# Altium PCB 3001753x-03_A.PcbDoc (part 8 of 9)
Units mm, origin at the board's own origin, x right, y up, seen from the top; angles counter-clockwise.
Board outline 210 x 130 mm, 8 copper layers (1-TOP, 2-GND, 3-INTOP, 4-PWR, 5-PWR, 6-INBOT, 7-GND, 8-BOTTOM), stack 1.646 mm thick; 676 components, 623 nets, 2861 pads, 2382 vias.
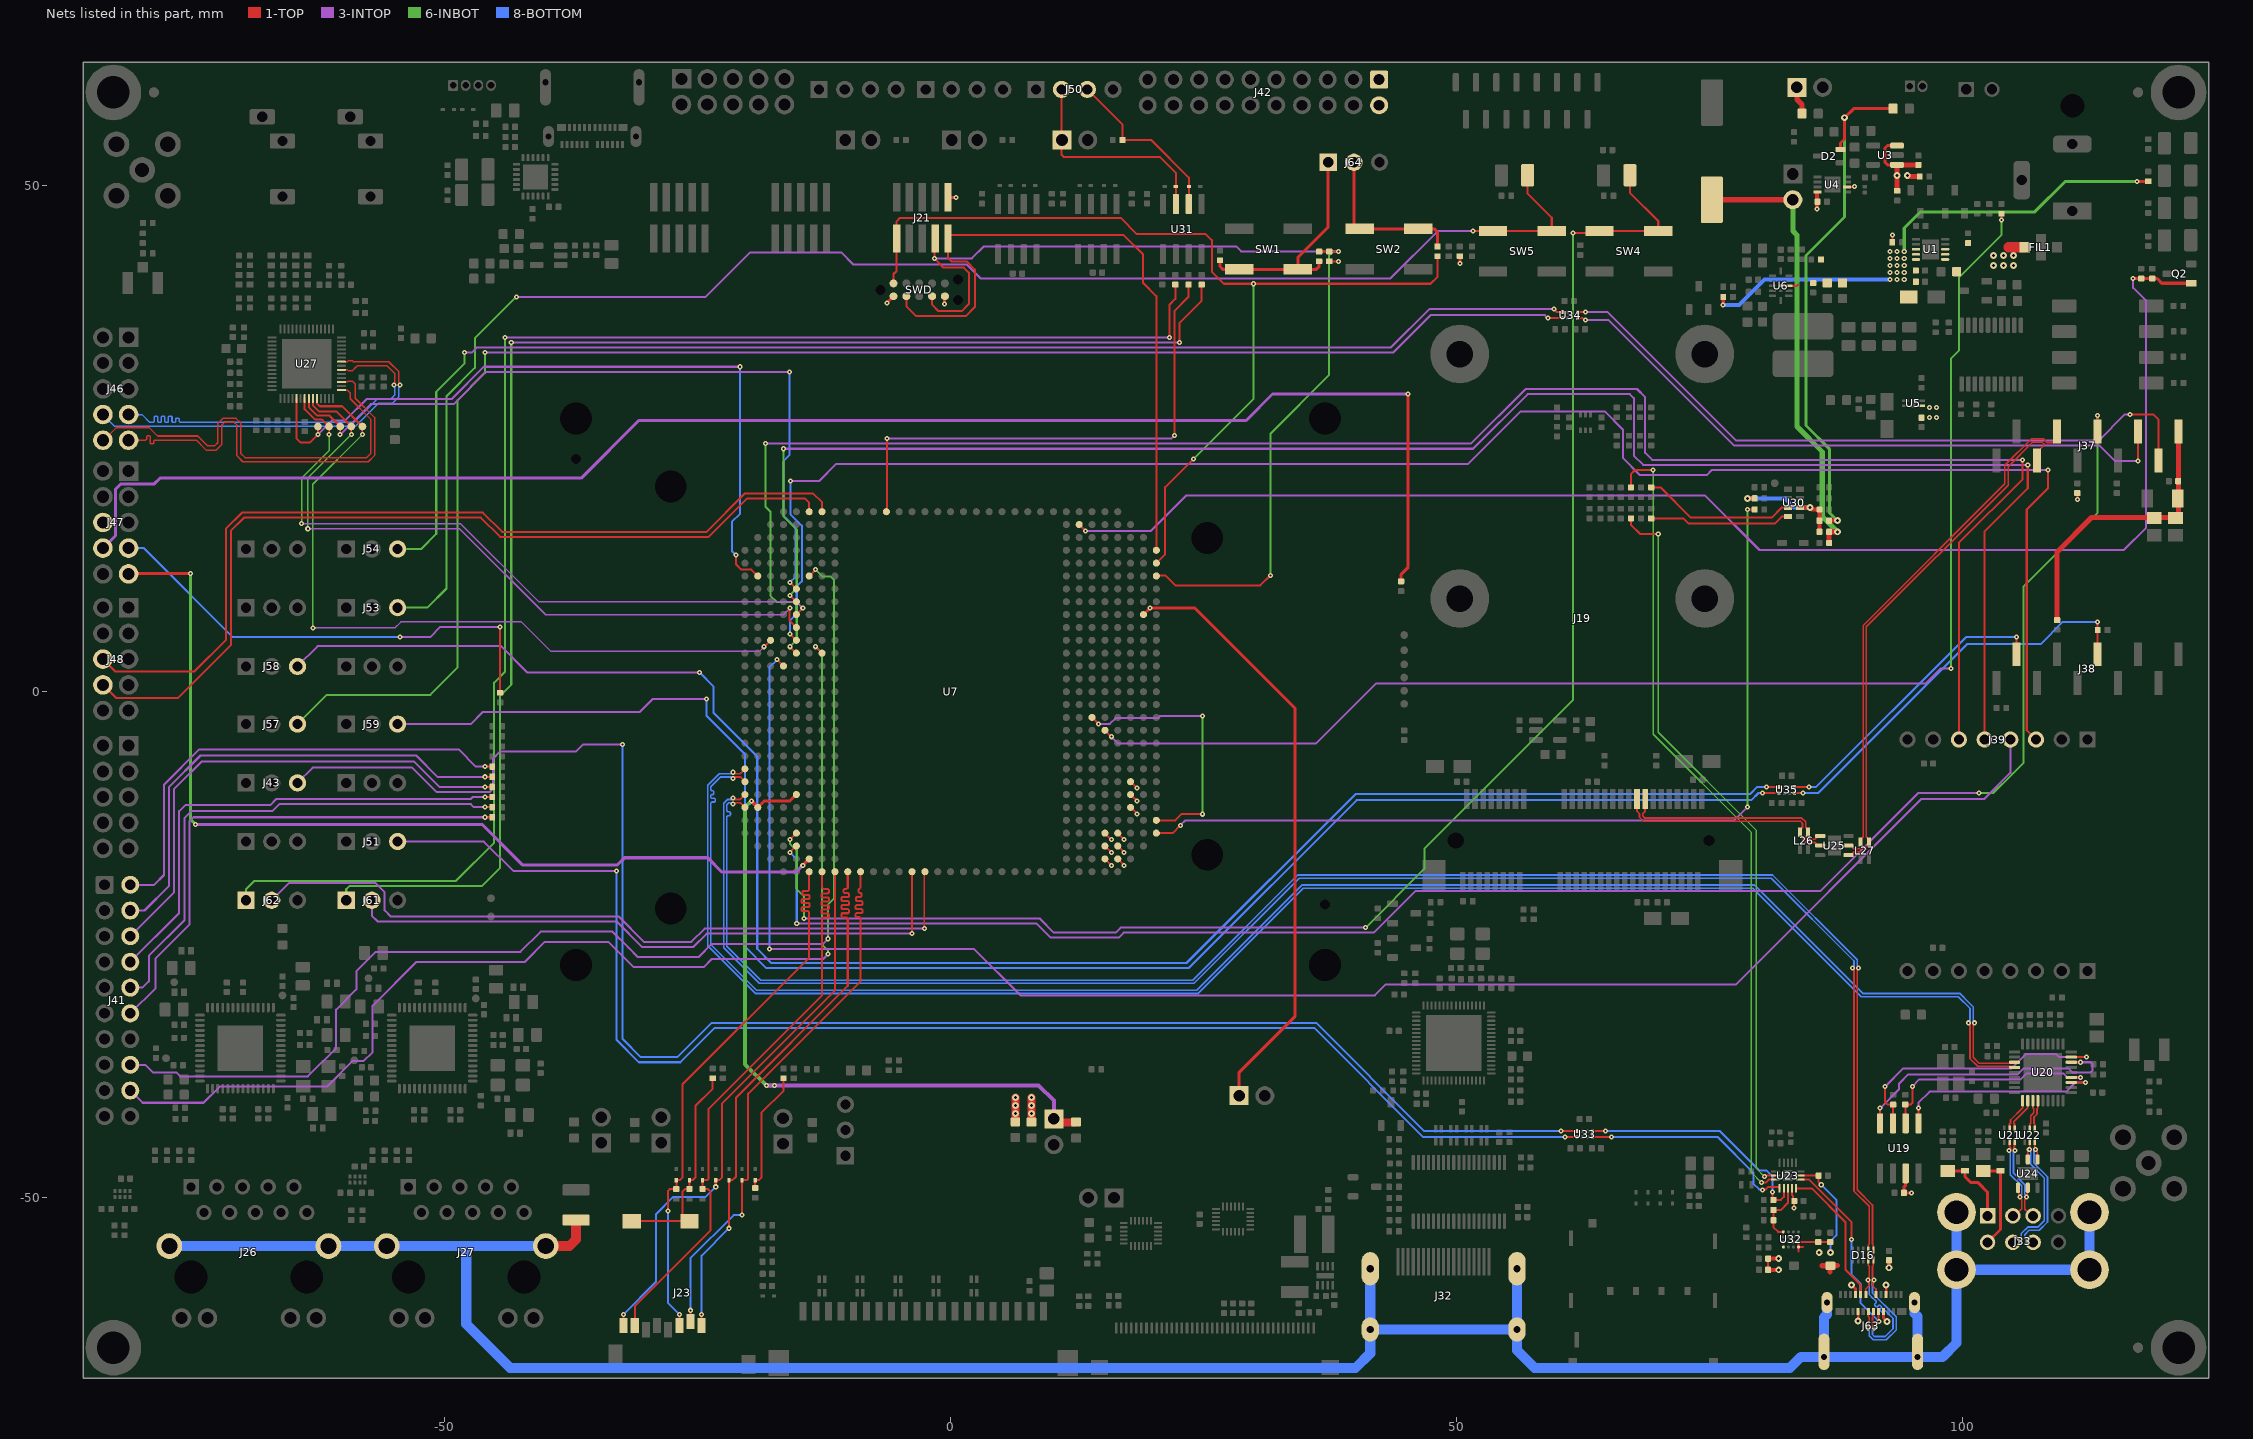
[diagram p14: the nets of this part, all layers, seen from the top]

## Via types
v1: diameter 0.5, hole 0.2, 1-TOP to 8-BOTTOM, 1547 vias
v2: diameter 0.68, hole 0.3, 1-TOP to 8-BOTTOM, 835 vias

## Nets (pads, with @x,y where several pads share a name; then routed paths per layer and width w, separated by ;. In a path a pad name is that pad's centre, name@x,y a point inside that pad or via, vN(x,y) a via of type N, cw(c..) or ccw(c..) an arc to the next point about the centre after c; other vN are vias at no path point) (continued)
POWER_BUTTON: J64.1 R2.1 R4.1 SW1.3 SW1.4 | length 22.9
  1-TOP w0.3: R4.1@26.6,42.62 26.6,42 26.873,41.727 SW1.3@28.5,41.727 33.4,41.727 SW1.4@34.3,41.727 ; R2.1@36.4,42.52 36.4,42 36.127,41.727 SW1.4@34.3,41.727 ; J64.1@37.3,52.194 37.3,45.9 34.3,42.9 SW1.4@34.3,41.727
POWER_LED: Q2.G R203.2 R204.1 U7.AG28 | length 141.4
  1-TOP w0.2: U7.AG28@12.7,16.51 v1(13.335,15.875)
  1-TOP w0.3: v1(116.8,40.8) 116.82,40.82 R204.1@117.6,40.82 R203.2@118.7,40.82 119.18,40.82 119.65,40.35 Q2.G@122.55,40.35
  3-INTOP w0.2: v1(13.335,15.875) 19.775,15.875 23.3,19.4 74.5,19.4 79.9,14 115.9,14 118.1,16.2 118.1,38.6 116.8,39.9 v1(116.8,40.8)
PWR_ON: R13.1 U7.AJ12 | length 134.2
  1-TOP w0.2: U7.AJ12@15.24,-3.81 v1(15.875,-4.445) ; v1(103.8,46.6) R13.1@103.8,47.22
  3-INTOP w0.2: v1(15.875,-4.445) 16.53,-5.1 36.1,-5.1 42,0.8 96.3,0.8 97.8,2.3 v1(98.8,2.3)
  6-INBOT w0.2: v1(98.8,2.3) 98.8,32.9 99.6,33.7 99.6,40.9 103.8,45.1 v1(103.8,46.6)
RESET_BUTTON: J64.2 R5.1 SW2.3 SW2.4 | length 15.8
  1-TOP w0.3: SW2.4@39.84,45.8 J64.2@39.84,52.3 ; SW2.4@40.4,45.727 SW2.3@46.2,45.727 47.773,45.727 48.1,45.4 R5.1@48.1,43.98
RS485_A: D19.2 J50.3 R236.1 U31.6 | length 17.1
  1-TOP w0.2: J50.3@13.5,59.5 17,56 17,54.5 19.8,54.5 23.525,50.775 23.525,49.899 U31.6@23.525,48.17
RS485_B: D20.2 J49.1 J50.2 U31.7 | length 21.6
  1-TOP w0.2: J50.2@10.96,59.5 10.96,54.319 10.96,53.04 11.2,52.8 20.7,52.8 22.255,51.245 22.255,49.8 U31.7@22.255,48.17
RS485_DE/RE: R234.1 U7.M29 | length 51.2
  1-TOP w0.2: U7.M29@-6.4,17.83 -6.3,17.93 v1(-6.3,25) ; v1(22.1,25.3) 22.1,37.6 23.5,39 R234.1@23.5,40.22
  3-INTOP w0.2: v1(-6.3,25) 21.8,25 v1(22.1,25.3)
RS485_RX: J62.1 R233.1 | length 148.9
  1-TOP w0.2: v1(21.6,35) 21.6,38.2 22.2,38.8 R233.1@22.2,40.22
  3-INTOP w0.2: v1(-44,35) v1(21.6,35)
  6-INBOT w0.2: J62.1@-69.6,-20.6 -69.6,-19.5 -68.8,-18.7 -48.9,-18.7 -45.1,-14.9 -45.1,0.9 -44,2 v1(-44,35)
RS485_TX: J61.1 R235.1 | length 142.2
  1-TOP w0.2: v1(22.6,34.5) 22.6,36.4 24.8,38.6 R235.1@24.8,40.22
  3-INTOP w0.2: v1(-43.4,34.5) v1(22.6,34.5)
  6-INBOT w0.2: J61.1@-59.7,-20.6 -59.7,-19.5 -59.4,-19.2 -46.3,-19.2 -44.5,-17.4 -44.5,-0.4 -43.4,0.7 v1(-43.4,34.5)
RTC_I2C_SCL: R230.2 U30.3 | length 14.9
  1-TOP w0.2: R230.2@69.4,20.18 70.12,20.18 73.1,17.2 81.1,17.2 82.1,18.2 U30.3@82.7,18.2
RTC_I2C_SDA: R231.2 U30.4 | length 14
  1-TOP w0.2: R231.2@69.2,17.1 72.4,17.1 72.9,16.6 81.4,16.6 82.1,17.3 U30.4@82.7,17.3
RTC_INT_N: R228.1 U7.AN4 | length 89.6
  1-TOP w0.2: U7.AN4@20.32,-13.97 21.93,-13.97 v1(22.7,-13.2) ; v1(78.7,18) R228.1@79.42,18
  3-INTOP w0.2: v1(22.7,-13.2) 23.2,-12.7 77.4,-12.7 v1(78.7,-11.4)
  6-INBOT w0.2: v1(78.7,-11.4) v1(78.7,18)
SAI3_MCLK: TP13.1 U7.B24 U27.5 | length 74.6
  1-TOP w0.2: U27.5@-64.6,28.97 -64.6,25 -64.2,24.6 -63.3,24.6 v1(-62.5,25.4) ; v1@-62.5,25.3 TP13.1@-62.5,26.2 ; v1(-21.2,13.5) -21.2,12.6 -20.665,12.065 -19.685,12.065 U7.B24@-19.05,11.43
  3-INTOP w0.2: v1(-62.5,25.4) -61.1,26.8 -59.8,26.8 -57.7,28.9 -49.3,28.9 -46.1,32.1 v1(-20.8,32.1)
  8-BOTTOM w0.2: v1(-21.2,13.5) -21.6,13.9 -21.6,16.8 -20.8,17.6 v1(-20.8,32.1)
SAI3_RXD: TP17.1 U7.E21 U27.7 | length 68.7
  1-TOP w0.15: v1(-61.4,25.4) TP17.1@-61.4,26.2
  1-TOP w0.2: U27.7@-63.8,28.97 -63.8,27.9 -62.8,26.9 -62.1,26.9 TP17.1@-61.4,26.2 ; U7.E21@-15.24,7.62 v1(-14.605,8.255)
  3-INTOP w0.15: v1(-64.1,16.6) -48.4,16.6 -40.7,8.9 -15.25,8.9 v1(-14.605,8.255)
  6-INBOT w0.15: v1(-64.1,16.6) -64.1,21.107 -61.4,23.807 v1(-61.4,25.4)
SAI3_TXC: TP14.1 U7.E23 U27.8 | length 75.2
  1-TOP w0.15: v1(-60.3,25.4) TP14.1@-60.3,26.2
  1-TOP w0.2: U27.8@-63.4,28.97 -63.4,28.1 -62.6,27.3 -61.4,27.3 TP14.1@-60.3,26.2 ; v1(-15.875,10.795) U7.E23@-15.24,10.16
  3-INTOP w0.2: v1(-60.3,25.4) -57.3,28.4 -49.1,28.4 -45.9,31.6 v1(-15.9,31.6)
  8-BOTTOM w0.2: v1(-15.9,31.6) -15.9,23.4 -16.5,22.8 -16.5,17.4 -15.3,16.2 -15.3,11.37 v1(-15.875,10.795)
SAI3_TXD: TP16.1 U7.E20 U27.9 | length 70.9
  1-TOP w0.15: v1(-59.2,25.4) TP16.1@-59.2,26.2
  1-TOP w0.2: U27.9@-63,28.97 -63,28.3 -62.4,27.7 -60.7,27.7 TP16.1@-59.2,26.2 ; v1@-15.9,8.3 -15.9,7.01 U7.E20@-15.24,6.35
  3-INTOP w0.15: v1(-63.5,16.1) -48.5,16.1 -40,7.6 -16.53,7.6 v1(-15.875,8.255)
  6-INBOT w0.15: v1(-63.5,16.1) -63.5,21.1 v1(-59.2,25.4)
SAI3_TXFS: TP15.1 U7.C19 U27.10 | length 75
  1-TOP w0.15: v1(-58.1,25.4) TP15.1@-58.1,26.2
  1-TOP w0.2: U27.10@-62.6,28.97 -62.6,28.5 -62.3,28.2 -60.1,28.2 TP15.1@-58.1,26.2 ; v1(-18.415,4.445) U7.C19@-17.78,5.08
  3-INTOP w0.15: v1(-63,6.3) -54.9,6.3 -54.3,6.9 -42.4,6.9 -39.475,3.975 -18.885,3.975 v1(-18.415,4.445)
  6-INBOT w0.15: v1(-63,6.3) -63,6.9 -63,20.5 v1(-58.1,25.4)
SD2_CD_B: D24.1 J23.9 J23.10 R91.2 R113.1 | length 21.2
  1-TOP w0.2: J23.10@-31.5,-52.3 J23.9@-25.8,-52.3 ; J23.9@-26.5,-52 -26.5,-49.4 -26.22,-49.12 R91.2@-25.8,-49.12 D24.1@-25.8,-48.25 -25.5,-48.25 -25.2,-47.95 -25.2,-40.9 -23.5,-39.2 R113.1@-23.5,-38.18
SD2_CLK: D30.1 R93.1 R240.1 | length 12.2
  1-TOP w0.2: R93.1@-19.3,-49.02 D30.1@-19.3,-48.25 -18.95,-48.25 -18.7,-48 -18.7,-41.6 -16.5,-39.4 R240.1@-16.5,-38.18
SD2_CMD: D28.1 J23.3 R90.1 U7.F1 | length 55.5
  1-TOP w0.2: v1(-27.9,-51.3) -27.9,-49.3 -27.72,-49.12 R90.1@-27.1,-49.12 D28.1@-27.1,-48.25 -26.75,-48.25 -26.5,-48 -26.5,-38.8 -13.97,-26.27 -13.97,-21.892 -13.97,-21.792 -14.087,-21.675 -14.638,-21.675 -14.718,-21.595 -14.718,-21.355 -14.638,-21.275 -13.997,-21.275 -13.917,-21.195 -13.917,-20.955 -13.997,-20.875 -14.638,-20.875 -14.718,-20.795 -14.718,-20.555 -14.638,-20.475 -13.997,-20.475 -13.917,-20.395 -13.917,-20.155 -13.997,-20.075 -14.558,-20.075 -14.638,-19.995 -14.638,-19.755 -14.558,-19.675 -14.087,-19.675 -13.97,-19.558 -13.97,-19 U7.F1@-13.97,-17.78 ; J23.3@-26.8,-62.6 v1(-26.8,-61.5)
  8-BOTTOM w0.2: v1(-27.9,-51.3) -27.9,-60.4 v1(-26.8,-61.5)
SD2_DATA0: D25.1 J23.7 R92.1 U7.G1 | length 58.8
  1-TOP w0.2: J23.7@-31.2,-62.6 -31.2,-60.7 -23.7,-53.2 -23.7,-49.4 -23.98,-49.12 R92.1@-24.5,-49.12 D25.1@-24.5,-48.25 -24.05,-48.25 -23.9,-48.1 -23.9,-41.2 -12.7,-30 -12.7,-22.925 -12.7,-22.425 -12.583,-22.308 -12.098,-22.308 -12.018,-22.228 -12.018,-21.988 -12.098,-21.908 -12.694,-21.908 -12.774,-21.828 -12.774,-21.588 -12.694,-21.508 -12.098,-21.508 -12.018,-21.428 -12.018,-21.188 -12.098,-21.108 -12.694,-21.108 -12.774,-21.028 -12.774,-20.788 -12.694,-20.708 -12.098,-20.708 -12.018,-20.628 -12.018,-20.388 -12.098,-20.308 -12.694,-20.308 -12.774,-20.228 -12.774,-19.988 -12.694,-19.908 -12.11,-19.908 -12.03,-19.828 -12.03,-19.588 -12.11,-19.508 -12.583,-19.508 -12.7,-19.391 -12.7,-19.125 U7.G1@-12.7,-17.78
SD2_DATA1: D27.1 J23.8 U7.H1 | length 55.5
  1-TOP w0.2: J23.8@-32.3,-62.6 v1(-32.3,-61.5) ; v1(-23.2,-48.9) D27.1@-23.2,-48.25 -22.85,-48.25 -22.6,-48 -22.6,-40.7 -11.43,-29.53 U7.H1@-11.43,-17.78
  8-BOTTOM w0.2: v1(-32.3,-61.5) -29.1,-58.3 -29.1,-51.6 -27.4,-49.9 -24.2,-49.9 v1(-23.2,-48.9)
SD2_DATA2: D29.1 J23.1 U7.J1 | length 55.5
  1-TOP w0.2: J23.1@-24.6,-62.6 v1(-24.6,-61.5) ; v1(-21.9,-53) D29.1@-21.9,-48.25 -21.55,-48.25 -21.2,-47.9 -21.2,-40.1 -10.16,-29.06 -10.16,-22.5 -10.16,-22.4 -10.277,-22.283 -10.718,-22.283 -10.798,-22.203 -10.798,-21.963 -10.718,-21.883 -10.124,-21.883 -10.044,-21.803 -10.044,-21.563 -10.124,-21.483 -10.718,-21.483 -10.798,-21.403 -10.798,-21.163 -10.718,-21.083 -10.124,-21.083 -10.044,-21.003 -10.044,-20.763 -10.124,-20.683 -10.718,-20.683 -10.798,-20.603 -10.798,-20.363 -10.718,-20.283 -10.124,-20.283 -10.044,-20.203 -10.044,-19.963 -10.124,-19.883 -10.485,-19.883 -10.565,-19.803 -10.565,-19.563 -10.485,-19.483 -10.277,-19.483 -10.16,-19.366 -10.16,-19.151 U7.J1@-10.16,-17.78
  8-BOTTOM w0.2: v1(-24.6,-61.5) -24.6,-55.7 v1(-21.9,-53)
SD2_DATA3: D26.1 J23.2 U7.K1 | length 55.5
  1-TOP w0.2: J23.2@-25.7,-62.2 v1(-25.7,-61.1) ; v1(-20.6,-51.7) D26.1@-20.6,-48.25 -20.15,-48.25 -20,-48.1 -20,-39.7 -8.89,-28.59 -8.89,-22.493 -8.89,-22.393 -9.007,-22.275 -9.31,-22.275 -9.39,-22.195 -9.39,-21.955 -9.31,-21.875 -8.798,-21.875 -8.718,-21.795 -8.718,-21.555 -8.798,-21.475 -9.31,-21.475 -9.39,-21.395 -9.39,-21.155 -9.31,-21.075 -8.798,-21.075 -8.718,-20.995 -8.718,-20.755 -8.798,-20.675 -9.288,-20.675 -9.368,-20.595 -9.368,-20.355 -9.288,-20.275 -8.89,-20.275 -8.81,-20.195 -8.81,-19.955 -8.89,-19.875 -9.007,-19.875 -9.087,-19.795 -9.087,-19.555 -9.007,-19.475 -8.89,-19.358 -8.89,-18.794 U7.K1@-8.89,-17.78
  8-BOTTOM w0.2: v1(-25.7,-61.1) -25.7,-55.96 -21.44,-51.7 v1(-20.6,-51.7)
SD2_VSELECT: U7.AH13 U7.AN5 | length 26
  1-TOP w0.2: U7.AH13@13.97,-2.54 v1(14.605,-3.175) ; U7.AN5@20.32,-12.7 22.2,-12.7 22.8,-12.1 v1(24.9,-12.1)
  3-INTOP w0.2: v1(14.605,-3.175) 15.725,-3.175 16.3,-2.6 20.5,-2.6 20.7,-2.4 v1(24.9,-2.4)
  6-INBOT w0.2: v1(24.9,-12.1) v1(24.9,-2.4)
SHLD: J26.SHLD1 J26.SHLD2 J27.SHLD1 J27.SHLD2 J32.M1 J32.M2 J32.M3 J32.M4 J33.SH1 J33.SH2 J33.SH3 J33.SH4 J63.MT1 J63.MT2 J63.MT3 J63.MT4 R100.2 | length 260.4
  1-TOP w1: J27.SHLD2@-39.99,-54.752 -37.652,-54.752 -37,-54.1 R100.2@-37,-52.2
  8-BOTTOM w1: J26.SHLD1@-77.17,-54.752 J26.SHLD2@-61.46,-54.752 J27.SHLD1@-55.7,-54.752 -47.845,-54.752 ; J27.SHLD2@-39.99,-54.752 -47.845,-54.752 ; J32.M2@41.45,-57 J32.M4@41.45,-63 ; J32.M3@55.95,-62.85 J32.M1@55.95,-57 ; J63.MT1@86.58,-60.345 86.58,-61.5 86.28,-61.8 J63.MT3@86.28,-65.705 ; J63.MT2@95.22,-60.245 95.22,-61.42 95.52,-61.72 J63.MT4@95.52,-65.605 ; J33.SH2@99.36,-51.42 J33.SH1@99.36,-57.1 ; J33.SH4@112.5,-51.42 J33.SH3@112.5,-57.1 J33.SH1@99.36,-57.1 ; -47.845,-54.752 -47.845,-62.455 -43.5,-66.8 40,-66.8 41.45,-65.35 J32.M4@41.45,-63 ; J32.M4@41.45,-63 J32.M3@55.95,-63 55.95,-65.05 57.7,-66.8 82.9,-66.8 83.995,-65.705 J63.MT3@86.28,-65.705 ; J63.MT3@86.28,-65.705 J63.MT4@95.52,-65.705 97.995,-65.705 99.36,-64.34 J33.SH1@99.36,-57.1
SPI8_MISO: J39.5 U7.E22 | length 176.5
  1-TOP w0.2: v1(-15.875,9.525) U7.E22@-15.24,8.89 ; J39.5@102.14,-4.725 102.14,15.84 106.4,20.1 v1(106.4,22.4)
  3-INTOP w0.2: v1(-16.5,24) 51.6,24 57,29.4 67.1,29.4 67.5,29 67.5,23.3 68.4,22.4 v1(106.4,22.4)
  6-INBOT w0.2: v1(-16.5,24) -16.5,17.3 -15.2,16 -15.2,10.2 v1(-15.875,9.525)
SPI8_MOSI: J39.6 U7.E18 | length 186.2
  1-TOP w0.2: v1(-15.875,4.445) U7.E18@-15.24,3.81 ; J39.6@99.6,-4.725 99.6,14.7 105.9,21 v1(105.9,22.9)
  3-INTOP w0.2: v1(-18.3,24.5) 51.393,24.5 56.793,29.9 67.8,29.9 68.6,29.1 68.6,23.6 69.3,22.9 v1(105.9,22.9)
  6-INBOT w0.2: v1(-18.3,24.5) -18.3,18.3 -17.8,17.8 -17.8,9.5 -17.18,8.88 -15.58,8.88 -15.2,8.5 -15.2,5.12 v1(-15.875,4.445)
SPI8_SCK: J39.4 U7.D17 | length 166.7
  1-TOP w0.2: v1(-17.145,3.175) U7.D17@-16.51,2.54
  3-INTOP w0.2: v1(-17.9,-25.4) 2.3,-25.4 6.9,-30 41.9,-30 43,-28.9 77.6,-28.9 95.9,-10.6 102.1,-10.6 104.68,-8.02 J39.4@104.68,-4.725
  8-BOTTOM w0.2: v1(-17.9,-25.4) -17.9,2.42 v1(-17.145,3.175)
SPI8_SS: J39.3 U7.E19 | length 176.3
  1-TOP w0.2: v1(-15.875,5.715) U7.E19@-15.24,5.08 ; J39.3@107.22,-4.725 106.3,-3.805 106.3,18 108.4,20.1 v1(108.4,21.9)
  3-INTOP w0.2: v1(-15.8,20.8) -13,20.8 -11.3,22.5 51.127,22.5 56.327,27.7 64.6,27.7 66.4,25.9 66.4,23.1 68.1,21.4 74.7,21.4 75.2,21.9 v1(108.4,21.9)
  8-BOTTOM w0.2: v1(-15.875,5.715) -15.875,7.025 -15.2,7.7 -15.2,10.4 -14.7,10.9 -14.7,16.4 -15.8,17.5 v1(-15.8,20.8)
SPKL_N: J46.8 U27.22 | length 39.6
  1-TOP w0.15: U27.22@-60.17,32.6 -59.6,32.6 -59.525,32.675 -59.075,32.675 -59,32.6 -55.5,32.6 -54.5,31.6 -54.5,30.4 v1(-54.4,30.3)
  8-BOTTOM w0.15: J46.8@-83.74,27.38 -82.56,26.2 -58.8,26.2 -56.5,28.5 -55.134,28.5 -54.5,29.134 -54.5,30.2 v1(-54.4,30.3)
SPKL_P: J46.7 U27.20 | length 39.6
  1-TOP w0.15: U27.20@-60.17,31.8 -59.6,31.8 -59.525,31.725 -59.075,31.725 -58.8,32 -58.6,32.2 -55.666,32.2 -54.9,31.434 -54.9,30.4 v1(-55,30.3)
  8-BOTTOM w0.15: J46.7@-81.2,27.38 -79.88,27.38 -79.1,26.6 -78.825,26.6 -78.75,26.6 -78.662,26.688 -78.662,27.142 -78.592,27.212 -78.382,27.212 -78.312,27.142 -78.312,26.67 -78.242,26.6 -78.032,26.6 -77.962,26.67 -77.962,27.142 -77.892,27.212 -77.682,27.212 -77.612,27.142 -77.612,26.67 -77.542,26.6 -77.332,26.6 -77.262,26.67 -77.262,27.142 -77.192,27.212 -76.982,27.212 -76.912,27.142 -76.912,26.67 -76.842,26.6 -76.632,26.6 -76.562,26.67 -76.562,26.965 -76.492,27.035 -76.282,27.035 -76.212,26.965 -76.212,26.688 -76.124,26.6 -75.907,26.6 -58.966,26.6 -56.666,28.9 -55.3,28.9 -54.9,29.3 -54.9,30.2 v1(-55,30.3)
SPKR_N: J46.10 U27.15 | length 41.2
  1-TOP w0.15: J46.10@-83.64,24.86 -82.4,26.1 -79.175,26.1 -78.335,25.26 -74.36,25.26 -73.375,24.275 -72.716,24.275 -72.4,24.591 -72.4,26.498 -71.898,27 -70.59,27 -70.1,26.51 -70.1,23.514 -69.711,23.125 -57.684,23.125 -57.3,23.509 -57.3,26.934 -59.3,28.934 -59.3,29.5 -59.6,29.8 U27.15@-60.17,29.8
SPKR_P: J46.9 U27.17 | length 41.2
  1-TOP w0.15: J46.9@-81.1,24.86 -79.575,24.86 -79.5,24.86 -79.412,24.948 -79.412,25.203 -79.342,25.273 -79.132,25.273 -79.062,25.203 -79.062,24.548 -78.992,24.478 -78.782,24.478 -78.712,24.548 -78.712,24.772 -78.624,24.86 -78.375,24.86 -74.526,24.86 -73.541,23.875 -72.55,23.875 -72,24.425 -72,26.332 -71.732,26.6 -70.756,26.6 -70.5,26.344 -70.5,23.307 -69.918,22.725 -57.518,22.725 -56.9,23.343 -56.9,27.1 -58.8,29 -58.8,30.4 -59.075,30.675 -59.525,30.675 -59.6,30.6 U27.17@-60.17,30.6
SUPERCAP: C9.1 J5.2 R227.2 R242.1 | length 44.6
  1-TOP w0.5: C9.1@75.1,48.6 J5.2@83.2,48.6 ; R242.1@86.78,14.7 R227.2@86.78,15.8 v2(87.6,15.8)
  6-INBOT w0.5: J5.2@83.2,48.6 83.2,45.5 83.6,45.1 83.6,26.2 86.1,23.7 86.1,17.3 v2(87.6,15.8)
SW_EN: J47.9 U7.F2 | length 94.8
  1-TOP w0.3: J47.9@-81.2,11.64 -81.14,11.7 v1(-75.1,11.7) ; v1(-14.605,-17.145) U7.F2@-13.97,-16.51
  3-INTOP w0.3: v1(-74.6,-13.1) -46.3,-13.1 -42.3,-17.1 -32.9,-17.1 -32.2,-16.4 -24,-16.4 -22.6,-17.8 -15.26,-17.8 v1(-14.605,-17.145)
  6-INBOT w0.3: v1(-75.1,11.7) -75.1,-12.6 v1(-74.6,-13.1)
SWD_CLK/PWR_IO: J21.4 R1.1 R2.2 SWD.4 U7.AN24 | length 103.8
  1-TOP w0.2: SWD.4@-1.83,39.065 -1.83,38.23 -1.2,37.6 1.1,37.6 1.8,38.3 1.8,41.4 1.3,41.9 -0.7,41.9 v1(-1.6,42.8) -1.6,44.698 J21.4@-1.53,44.768 ; U7.AN24@20.32,11.43 20.39,11.5 21.2,11.5 22.2,10.5 30.6,10.5 v1(31.6,11.5) ; R2.2@36.4,43.48 R1.1@37.4,43.48 37.42,43.5 v1(38.3,43.5)
  3-INTOP w0.2: v1(-1.6,42.8) 2.1,42.8 3.3,44 28.2,44 28.7,43.5 v1(38.3,43.5)
  6-INBOT w0.2: v1(31.6,11.5) 31.6,25.5 37.4,31.3 37.4,43.1 37.8,43.5 v1(38.3,43.5)
SWD_DIO: J21.2 SWD.2 U7.AN26 | length 67.5
  1-TOP w0.2: SWD.2@-4.37,39.065 -4.37,38.07 -3.4,37.1 1.5,37.1 2.4,38 2.4,41.7 1.6,42.5 0.1,42.5 -0.26,42.86 J21.2@-0.26,44.768 J21.2@0.072,45.1 ; J21.2@-0.2,45.1 J21.2@0.072,45.1 ; U7.AN26@20.32,13.97 20.32,39.08 19,40.4 19,43.2 17.1,45.1 J21.2@0.072,45.1
SWIN: J47.7 R41.1 | length 47.3
  1-TOP w0.2: R41.1@-44.5,-0.1 v1(-44.5,6.4)
  3-INTOP w0.2: v1(-54.4,5.4) -51.4,5.4 -50.4,6.4 v1(-44.5,6.4)
  8-BOTTOM w0.2: J47.7@-81.2,14.18 -79.68,14.18 -70.9,5.4 v1(-54.4,5.4)
SWOUT: J47.8 R42.1 | length 156.7
  1-TOP w0.3: R42.1@44.5,10.9 44.5,11.6 45.2,12.3 v1(45.2,29.4)
  3-INTOP w0.3: J47.8@-83.74,14.18 -82.5,15.42 -82.5,20 -82,20.5 -78.7,20.5 -78.1,21.1 -36.5,21.1 -30.8,26.8 29.2,26.8 31.8,29.4 v1(45.2,29.4)
SYS_RESET: J21.10 R5.2 SWD.10 U7.AN25 | length 100.4
  1-TOP w0.2: SWD.10@-5.64,40.335 -5.64,41.26 -5.34,41.56 J21.10@-5.34,44.768 J21.10@-5.34,45.76 ; J21.10@-5.5,43.736 -5.5,45.6 J21.10@-5.34,45.76 ; J21.10@-5.3,45.8 J21.10@-5.34,45.76 ; U7.AN25@20.32,12.7 21.2,13.58 21.2,20.2 v1(24,23) ; R5.2@48.1,43.02 48.1,41 47.4,40.3 27,40.3 25.8,41.5 25.8,44.6 25.2,45.2 18.4,45.2 16.8,46.8 -5,46.8 -5.34,46.46 J21.10@-5.34,45.76
  6-INBOT w0.2: v1(24,23) 29.9,28.9 v1(29.9,40.3)
TAMPER0: J48.6 U7.G29 | length 88.2
  1-TOP w0.2: J48.6@-83.74,3.24 -82.5,2 -74.7,2 -71.6,5.1 -71.6,16.1 -70,17.7 -46.2,17.7 -44.3,15.8 -24.107,15.8 -20.307,19.6 -13.6,19.6 -12.7,18.7 U7.G29@-12.7,17.78
TAMPER1: J48.8 U7.F29 | length 87.7
  1-TOP w0.2: J48.8@-83.74,0.7 -82.44,-0.6 -76.3,-0.6 -71.1,4.6 -71.1,15.9 -69.8,17.2 -46.407,17.2 -44.507,15.3 -23.9,15.3 -20.1,19.1 -14.4,19.1 -13.97,18.67 U7.F29@-13.97,17.78
U1_N: U20.1 U21.2 | length 3.3
  1-TOP w0.168: U21.2@104.6,-43.15 104.6,-42.7 104.691,-42.609 104.691,-42.309 105.9,-41.1 U20.1@105.9,-40.4
U1_P: U20.2 U21.1 | length 3.4
  1-TOP w0.168: U21.1@105.1,-43.15 105.1,-42.7 105.009,-42.609 105.009,-42.491 106.4,-41.1 U20.2@106.4,-40.4
U2_N: U20.3 U22.2 | length 2.9
  1-TOP w0.168: U22.2@106.6,-43.15 106.6,-42.7 106.691,-42.609 106.691,-41.9 106.991,-41.6 106.991,-41.191 106.9,-41.1 U20.3@106.9,-40.4
U2_P: U20.4 U22.1 | length 2.9
  1-TOP w0.168: U22.1@107.1,-43.15 107.1,-42.7 107.009,-42.609 107.009,-42.454 107.009,-42.3 107.009,-42.032 107.309,-41.732 107.309,-41.191 107.4,-41.1 U20.4@107.4,-40.4
UART7_RX: J62.2 U7.R1 | length 74.8
  1-TOP w0.15: v1(-2.6,-23.4) -2.6,-17.84 U7.R1@-2.54,-17.78
  3-INTOP w0.2: J62.2@-67.06,-20.6 -65.36,-18.9 -56.8,-18.9 -55.9,-19.8 -55.9,-21.6 -55.3,-22.2 -32.793,-22.2 -30.293,-24.7 -25.6,-24.7 -24.3,-23.4 v1(-2.6,-23.4)
UART7_TX: J61.2 U7.P1 | length 62.8
  1-TOP w0.2: U7.P1@-3.81,-17.78 -3.81,-23.89 v1(-3.8,-23.9)
  3-INTOP w0.2: J61.2@-57.16,-20.6 -57.16,-22.14 -56.6,-22.7 -33,-22.7 -30.5,-25.2 -25.4,-25.2 -24.1,-23.9 v1(-3.8,-23.9)
ULED/BUTTON_1: D17.K SW4.1 SW4.2 U7.E4 | length 157.8
  1-TOP w0.2: v1(-15.875,-14.605) U7.E4@-15.24,-13.97 ; v1(61.5,45.3) 63.9,45.3 SW4.1@64.1,45.5 SW4.2@69.9,45.5 69.9,46.5 67.1,49.3 D17.K@67.1,51.025
  3-INTOP w0.2: v1(-14.5,-22.4) 8.8,-22.4 10.2,-23.8 16.3,-23.8 16.8,-23.3 v1(41,-23.3)
  6-INBOT w0.2: v1(-15.875,-14.605) -15.875,-15.025 -15.2,-15.7 -15.2,-19.5 -14.5,-20.2 v1(-14.5,-22.4) ; v1(41,-23.3) 46.8,-17.5 46.8,-15.5 61.5,-0.8 v1(61.5,45.3)
ULED/BUTTON_2: D18.K J53.3 SW5.1 SW5.2 | length 150.9
  1-TOP w0.2: v1(51.6,45.5) SW5.1@53.581,45.5 SW5.2@59.381,45.5 59.381,46.819 57,49.2 D18.K@57,51.025
  3-INTOP w0.2: v1(-42.9,39) -24.2,39 -19.8,43.4 -10.8,43.4 -9.6,42.2 1.6,42.2 3,40.8 43.4,40.8 48.1,45.5 v1(51.6,45.5)
  6-INBOT w0.2: J53.3@-54.62,8.3 -51.7,8.3 -49.8,10.2 -49.8,29.2 -47,32 -47,34.9 v1(-42.9,39)
USB_HUB_N: U7.A8 U20.30 | length 166
  1-TOP w0.168: v1(-21.5,-8.555) -21.359,-8.414 -20.796,-8.414 U7.A8@-20.32,-8.89 ; v1(101.159,-32.7) 101.018,-32.841 101.018,-36.118 101.591,-36.691 105.009,-36.691 U20.30@105.1,-36.6
  8-BOTTOM w0.168: v1(-21.5,-8.555) -21.641,-8.414 -22.714,-8.414 -23.682,-9.382 -23.682,-9.557 -23.682,-9.687 -23.584,-9.785 -23.467,-9.785 -23.394,-9.859 -23.394,-10.079 -23.467,-10.153 -23.608,-10.153 -23.682,-10.227 -23.682,-10.447 -23.608,-10.521 -23.33,-10.521 -23.256,-10.595 -23.256,-10.815 -23.33,-10.889 -23.584,-10.889 -23.682,-10.987 -23.682,-11.439 -23.682,-24.968 -19.168,-29.482 24.318,-29.482 34.718,-19.082 79.382,-19.082 90.1,-29.8 99.675,-29.8 100.6,-30.725 ; 100.618,-30.743 101.018,-31.143 101.018,-31.275 101.018,-32.559 v1(101.159,-32.7)
USB_HUB_P: U7.A9 U20.31 | length 166
  1-TOP w0.168: v1(-21.5,-7.955) -21.359,-8.096 -20.796,-8.096 U7.A9@-20.32,-7.62 ; v1(100.559,-32.7) 100.7,-32.841 100.7,-36.25 101.459,-37.009 105.009,-37.009 U20.31@105.1,-37.1
  8-BOTTOM w0.168: v1(-21.5,-7.955) -21.641,-8.096 -22.846,-8.096 -24,-9.25 -24,-25.1 -19.3,-29.8 24.45,-29.8 34.85,-19.4 79.25,-19.4 89.968,-30.118 99.543,-30.118 100.7,-31.275 100.7,-32.559 v1(100.559,-32.7)
USB_OTG1_N: D16.1 D16.10 J63.A7 J63.B7 U7.A6 | length 183.4
  1-TOP w0.168: v1(-21.5,-11.095) -21.359,-10.954 -20.796,-10.954 U7.A6@-20.32,-11.43 ; v1(89.7,-27.3) 89.559,-27.441 89.559,-49.209 91.059,-50.709 91.059,-54.554 91.15,-54.645 D16.1@91.15,-55.145 D16.10@91.15,-56.15 91.15,-56.65 91.059,-56.741 91.059,-57.959 v1(91.2,-58.1) 91.059,-58.241 91.059,-58.659 91.4,-59 J63.A7@91.4,-59.535 ; v1(90.6,-62.9) 90.741,-62.759 90.741,-61.8 90.65,-61.709 J63.B7@90.65,-61.235
  8-BOTTOM w0.168: v1(-21.5,-11.095) -21.641,-10.954 -21.9,-10.954 -22.1,-11.154 -22.1,-11.772 -22.002,-11.87 -21.81,-11.87 -21.736,-11.944 -21.736,-12.164 -21.81,-12.238 -22.002,-12.238 -22.1,-12.336 -22.1,-25.15 -18.758,-28.492 23.908,-28.492 34.3,-18.1 81.191,-18.1 89.559,-26.468 89.559,-27.159 v1(89.7,-27.3) ; v1(90.6,-62.9) 90.741,-63.041 90.741,-63.632 91.127,-64.018 92.432,-64.018 93.4,-63.05 93.4,-61.75 91.059,-59.409 91.059,-58.241 v1(91.2,-58.1)
USB_OTG1_P: D16.2 D16.9 J63.A6 J63.B6 U7.A7 | length 183.4
  1-TOP w0.168: v1(-21.5,-10.495) -21.359,-10.636 -20.796,-10.636 U7.A7@-20.32,-10.16 ; v1(89.1,-27.3) 89.241,-27.441 89.241,-49.341 90.741,-50.841 90.741,-54.554 90.65,-54.645 D16.2@90.65,-55.145 ; J63.A6@90.4,-59.535 90.4,-59 90.741,-58.659 90.741,-58.241 v1(90.6,-58.1) 90.741,-57.959 90.741,-56.741 90.65,-56.65 D16.9@90.65,-56.15 D16.2@90.65,-55.15 ; J63.B6@91.15,-61.235 91.15,-61.709 91.059,-61.8 91.059,-62.759 v1(91.2,-62.9)
  8-BOTTOM w0.168: v1(-21.5,-10.495) -21.641,-10.636 -22.032,-10.636 -22.418,-11.022 -22.418,-25.282 -18.89,-28.81 24.04,-28.81 34.432,-18.418 81.059,-18.418 89.241,-26.6 89.241,-27.159 v1(89.1,-27.3) ; v1(90.6,-58.1) 90.741,-58.241 90.741,-59.541 91.1,-59.9 91.159,-59.959 91.42,-60.22 91.42,-60.359 91.291,-60.487 91.291,-60.591 91.447,-60.748 91.551,-60.748 91.697,-60.601 91.801,-60.601 91.958,-60.758 91.958,-60.862 91.811,-61.008 91.811,-61.112 91.968,-61.268 92.072,-61.268 92.2,-61.139 92.339,-61.139 92.474,-61.274 92.533,-61.333 93.082,-61.882 93.082,-62.918 92.3,-63.7 91.259,-63.7 91.059,-63.5 91.059,-63.041 v1(91.2,-62.9)
USB_PCIe_D_N: J19.36 L26.3 U25.2 | length 22.1
  1-TOP w0.168: J19.36@67.8,-10.6 67.8,-11.8 68.041,-12.041 68.041,-12.391 68.45,-12.8 83.95,-12.8 84.141,-12.991 84.141,-13.404 84.043,-13.502 84.016,-13.502 83.9,-13.618 83.9,-14.118 84.016,-14.234 84.043,-14.234 84.141,-14.332 84.141,-14.574 84.451,-14.884 85.028,-14.884 85.386,-14.884 85.484,-14.982 85.484,-15.084 85.6,-15.2 U25.2@85.9,-15.2
USB_PCIe_D_P: J19.38 L26.2 U25.1 | length 21.6
  1-TOP w0.168: J19.38@68.6,-10.6 68.6,-11.8 68.359,-12.041 68.359,-12.259 68.582,-12.482 84.082,-12.482 84.459,-12.859 84.459,-13.404 84.557,-13.502 84.584,-13.502 84.7,-13.618 84.7,-14.118 84.584,-14.234 84.579,-14.234 84.485,-14.328 84.485,-14.468 84.583,-14.566 85.16,-14.566 85.386,-14.566 85.484,-14.468 85.484,-14.366 85.6,-14.25 U25.1@85.9,-14.25
USBC_ALERT_N_1V8: J43.3 U33.4 | length 167.4
  1-TOP w0.2: v1(60.3,-43.4) 60.307,-43.393 U33.4@61.893,-43.393
  3-INTOP w0.2: J43.3@-64.52,-9 -63.02,-7.5 -53.2,-7.5 -50.8,-9.9 -45.5,-9.9 -45.2,-9.6 -45.2,-6.6 -44.5,-5.9 -37,-5.9 -36.3,-5.2 v1(-32.4,-5.2)
  8-BOTTOM w0.2: v1(-32.4,-5.2) -32.4,-34.3 -30.6,-36.1 -27,-36.1 -23.6,-32.7 36.1,-32.7 46.8,-43.4 v1(60.3,-43.4)
USBC_ALERT_N_3V3: R51.2 U23.10 U33.1 | length 24
  1-TOP w0.2: U33.1@63.393,-43.393 63.4,-43.4 v1(64.7,-43.4) ; v1(81.2,-49.427) 81.2,-50.12 R51.2@81.28,-50.2 82,-50.2 82.3,-49.9 U23.10@82.3,-49.05
  8-BOTTOM w0.2: v1(64.7,-43.4) 76,-43.4 79.9,-47.3 80.6,-47.3 81.2,-47.9 v1(81.2,-49.427)
USBC_CC1: J63.A5 U23.13 | length 14
  1-TOP w0.2: U23.13@83.5,-49.05 85.05,-49.05 88.4,-52.4 88.4,-57.1 89.9,-58.6 J63.A5@89.9,-59.535
USBC_CC2: J63.B5 U23.14 | length 18.7
  1-TOP w0.2: U23.14@83.95,-48.2 84.8,-48.2 89,-52.4 v1(89,-54.1) ; J63.B5@91.65,-61.235 91.65,-62.15 v1(91.7,-62.2)
  8-BOTTOM w0.2: v1(89,-54.1) 89,-57.6 89.9,-58.5 89.9,-60.4 v1(91.7,-62.2)
USBC_FAULT_N: R149.2 R192.2 U23.11 U32.A4 | length 6
  1-TOP w0.2: U32.A4@82.25,-53.35 81.75,-53.35 81.28,-52.88 R149.2@81.28,-52.2 R192.2@81.28,-51.2 82,-51.2 82.7,-50.5 U23.11@82.7,-49.05
USBC_INT_B_1V8: J51.3 U33.5 | length 141.2
  1-TOP w0.2: v1(60.7,-44) 61.886,-44 U33.5@61.893,-43.993
  3-INTOP w0.2: J51.3@-54.62,-14.8 -46.1,-14.8 -43.2,-17.7 v1(-33,-17.7)
  8-BOTTOM w0.2: v1(-33,-17.7) -33,-34.4 -30.8,-36.6 -26.707,-36.6 -23.307,-33.2 35.9,-33.2 46.7,-44 v1(60.7,-44)
USBC_INT_B_3V3: U23.9 U33.8 | length 21.6
  1-TOP w0.2: U33.8@63.4,-44 v1(65.3,-44) ; v1(80.2,-49.2) 80.248,-49.152 80.529,-49.152 80.781,-48.9 81.9,-48.9 U23.9@81.9,-49.05
  8-BOTTOM w0.2: v1(65.3,-44) 75.8,-44 79.3,-47.5 79.3,-48.6 79.861,-49.161 80.161,-49.161 v1(80.2,-49.2)
USBC_SCL: R46.2 U23.8 | length 80.3
  1-TOP w0.2: R46.2@66.99,19.97 66.99,19.995 67.175,20.18 R46.2@67.2,20.18 67.2,21.5 67.6,21.9 v1(69.4,21.9) ; v1(80.1,-48.5) 80.5,-48.5 80.8,-48.2 U23.8@81.45,-48.2
  6-INBOT w0.15: v1(69.4,21.9) 69.4,-4.207 79.1,-13.907 79.1,-14.007 79.1,-30.704 79.1,-47.5 v1(80.1,-48.5)
USBC_SDA: R47.2 U23.7 | length 72.6
  1-TOP w0.2: R47.2@67.2,17.12 67.2,16.5 68.1,15.6 v1(69.9,15.6) ; v1(80.4,-47.9) 80.5,-47.8 U23.7@81.45,-47.8
  6-INBOT w0.15: v1(69.9,15.6) 69.9,-4 79.6,-13.7 79.6,-13.8 79.6,-30.4 79.6,-47.1 v1(80.4,-47.9)
USBC_VBUS: C147.2 C188.2 C199.2 C200.2 D21.K J63.A4 J63.A9 J63.B4 J63.B9 U23.15 U32.C2 U32.D1 U32.D2 | length 22.5
  1-TOP w0.2: U32.C2@83.25,-54.35 U32.D2@83.75,-54.35 ; 83.75,-55.3 U32.D1@83.75,-54.85 ; U32.D1@83.75,-54.75 U32.D1@83.75,-54.85 ; U23.15@83.95,-47.8 C188.2@85.74,-47.8 85.74,-48.44 v1(86,-48.7) ; 84.208,-54.85 U32.D1@83.75,-54.85 ; C200.2@86.9,-54.36 86.89,-54.35 U32.D2@83.75,-54.35 ; U32.D1@83.75,-54.85 U32.D2@83.75,-54.35
  1-TOP w0.25: v2(89,-58.6) 89.4,-59 J63.A4@89.4,-59.535 ; v2(89.65,-62.15) J63.B9@89.65,-61.235 ; J63.B4@92.15,-61.235 92.15,-61.85 v2(92.5,-62.2) ; J63.A9@92.4,-59.535 v2(92.4,-58.62)
  1-TOP w0.3: v2(92.7,-56.9) C147.2@92.7,-56.16
  1-TOP w0.5: 86.1,-56.7 D21.K@86.886,-56.7 ; D21.K@86.88,-56.688 D21.K@86.886,-56.688 ; 86.886,-57.3 D21.K@86.886,-56.7 ; 87.6,-56.688 D21.K@86.9,-56.688 ; D21.K@86.886,-56.7 D21.K@86.886,-56.688 ; D21.K@86.886,-56.7 D21.K@86.9,-56.7 D21.K@86.9,-56.688 ; D21.K@86.886,-56.688 D21.K@86.9,-56.688
  8-BOTTOM w0.2: v1(86,-48.7) 87.5,-50.2 87.5,-53.7 86.9,-54.3 v2(86.9,-55.4)
  other v2: 85.8,-55.4
USBH1_D_N: J33.A2 U21.5 U24.1 | length 9.5
  1-TOP w0.168: v1(104.55,-45.3) 104.591,-45.3 104.691,-45.2 104.691,-44.991 104.6,-44.9 U21.5@104.6,-44.45 ; J33.A2@104.93,-51.77 105.098,-51.77 105.796,-51.072 105.796,-50.156 105.63,-49.99 v1(105.63,-49.9) 105.5,-49.77 105.5,-49.02 U24.1@105.48,-49
  8-BOTTOM w0.168: v1(104.55,-45.3) 104.682,-45.432 104.682,-47.702 105.796,-48.816 105.796,-49.644 105.63,-49.81 v1(105.63,-49.9)
USBH1_D_P: J33.A3 U21.6 U24.2 | length 9.5
  1-TOP w0.168: U21.6@105.1,-44.45 105.1,-44.9 105.009,-44.991 105.009,-45.2 105.109,-45.3 v1(105.15,-45.3) ; U24.2@106.43,-49 106.344,-49.086 106.344,-49.836 v1(106.28,-49.9) 106.28,-49.99 106.114,-50.156 106.114,-51.122 106.762,-51.77 J33.A3@106.93,-51.77
  8-BOTTOM w0.168: v1(105.15,-45.3) 105,-45.45 105,-47.57 106.114,-48.684 106.114,-49.644 106.28,-49.81 v1(106.28,-49.9)
USBH1_OC_N: R139.1 U19.2 U20.13 | length 22.4
  1-TOP w0.2: R139.1@94.3,-40.8 94.3,-42.585 U19.2@94.345,-42.63 ; R139.1@94.3,-40.78 94.82,-40.78 95,-40.6 v1(95,-39) ; U20.13@110.7,-38.1 v1(111.6,-38.1)
  3-INTOP w0.2: v1(95,-39) 95.7,-38.3 105.7,-38.3 106.3,-37.7 109.9,-37.7 110.3,-38.1 v1(111.6,-38.1)
USBH1_PWR_EN: U19.1 U20.12 | length 20.8
  1-TOP w0.2: v1(95.6,-41.1) 95.6,-42.615 U19.1@95.615,-42.63 ; U20.12@110.7,-38.6 v1(112.1,-38.6)
  3-INTOP w0.2: v1(95.6,-41.1) 95.6,-40.6 96.7,-39.5 110.2,-39.5 111.1,-38.6 v1(112.1,-38.6)
USBH2_D_N: J33.B2 U22.5 U24.5 | length 13.7
  1-TOP w0.168: U24.5@106.4,-46.2 106.4,-45.35 v1(106.55,-45.2) 106.6,-45.15 U22.5@106.6,-44.45
  8-BOTTOM w0.168: J33.B2@104.93,-54.39 105.297,-54.39 105.652,-54.035 105.673,-54.035 105.771,-53.936 105.771,-53.509 106.398,-52.882 107.398,-52.882 108.03,-52.25 108.03,-48.03 106.691,-46.691 106.691,-45.341 v1(106.55,-45.2)
USBH2_D_P: J33.B3 U22.6 U24.4 | length 13.9
  1-TOP w0.168: v1@107.009,-45.109 v1@107.125,-45.225 ; U22.6@107.1,-44.45 107.1,-45.15 v1(107.15,-45.2) v1@107.125,-45.225 ; U24.4@107.35,-46.2 107.35,-45.45 v1@107.125,-45.225
  8-BOTTOM w0.168: J33.B3@106.93,-54.39 106.563,-54.39 106.208,-54.035 106.187,-54.035 106.089,-53.936 106.089,-53.641 106.53,-53.2 107.53,-53.2 108.348,-52.382 108.348,-47.898 107.009,-46.559 107.009,-45.341 v1(107.15,-45.2)
USBH2_OC_N: R140.1 U19.3 U20.17 | length 27.1
  1-TOP w0.2: v1(92.3,-39) 92.3,-40.5 92.58,-40.78 R140.1@93.1,-40.78 93.075,-40.805 U19.3@93.075,-42.63 ; U20.17@110.7,-36.1 v1(112.2,-36.1)
  3-INTOP w0.2: v1(92.3,-39) 94.1,-37.2 104.8,-37.2 106.2,-35.8 109.2,-35.8 109.5,-36.1 v1(112.2,-36.1)
USBH2_PWR_EN: U19.4 U20.16 | length 27.4
  1-TOP w0.2: v1(91.8,-41.1) 91.805,-41.105 U19.4@91.805,-42.63 ; U20.16@110.7,-36.6 v1(111.6,-36.6)
  3-INTOP w0.2: v1@91.86,-41.08 93.7,-39.24 93.7,-38.7 94.6,-37.8 105.4,-37.8 106,-37.2 110.4,-37.2 110.8,-37.6 112.6,-37.6 112.8,-37.4 112.8,-36.8 112.6,-36.6 v1(111.6,-36.6)
VBACKUP: C192.2 R225.2 R226.1 R227.1 U30.6 | length 11.5
  1-TOP w0.4: v2(78.7,19.1) R225.2@79.42,19.1 ; U30.6@83.9,18.2 v2(84.9,18.2) 85.1,18 C192.2@85.84,18 85.84,15.82 R227.1@85.82,15.8
  8-BOTTOM w0.4: v2(78.7,19.1) 82.4,19.1 83.3,18.2 v2(84.9,18.2)
VCC_MCA: C10.1 J3.1 J9.1 J21.1 J42.1 J42.2 J47.6 R1.2 R3.2 R16.2 SWD.1 SWD.5 U4.2 U4.8 U7.AM21 | length 69.3
  1-TOP w0.2: R1.2@37.4,42.52 38.28,42.52 v1(38.3,42.5) ; U4.8@85.6,49.3 U4.8@85.65,49.35 ; U4.2@88.25,49.85 89.25,49.85 v1(89.3,49.9)
  1-TOP w0.3: v1(-6.3,38.4) -6.3,38.405 SWD.1@-5.64,39.065 ; v1(-0.6,38.3) -0.6,39.025 SWD.5@-0.56,39.065 SWD.5@-0.56,39.046 ; J21.1@-0.04,48.832 v1(0.53,48.832) ; U7.AM21@19.05,7.62 v1(19.685,8.255) 24.145,8.255 34,-1.6 34,-32.1 28.5,-37.6 J9.1@28.5,-39.9 ; v1(50.3,42.3) R3.2@50.3,42.97
  1-TOP w0.4: v1(85.6,47.7) U4.8@85.6,49.302
  1-TOP w0.5: J3.1@83.6,59.7 83.6,58.5 84.1,58 R16.2@84.1,57.1
VCC_RTC: D2.2 R17.2 R226.2 | length 51.9
  1-TOP w0.3: D2.2@87.9,53.55 87.9,54.2 88.3,54.6 v2(88.3,56.7) 89.2,57.6 R17.2@93.1,57.6
  1-TOP w0.4: R226.2@86.78,16.9 v2(87.6,16.9)
  6-INBOT w0.3: v2(87.6,16.9) 86.8,17.7 86.8,23.99 84.5,26.29 84.5,43.1 88.3,46.9 v2@88.3,56.658
VCC_USB_A: D22.K J33.A1 L23.1 | length 7.2
  1-TOP w0.3: L23.1@98.5,-47.326 D22.K@100.2,-47.324 ; 100.2,-47.624 100.2,-47.9 100.8,-48.5 101.5,-48.5 102.43,-49.43 J33.A1@102.43,-51.77
VCC_USB_B: D23.K J33.B1 L22.1 | length 9.8
  1-TOP w0.3: J33.B1@102.43,-54.39 103.7,-53.12 103.7,-47.467 103.583,-47.35 102.6,-47.35 L22.1@102,-47.35 102.024,-47.326 L22.1@102.6,-47.326
VIN: C1.2 C8.2 FIL1.3 R7.2 R8.2 R9.2 R10.2 U1.1 U1.2 U1.3 U3.1 U3.3 | length 12
  1-TOP w0.2: R9.2@93.02,44.4 v1(93.02,45.1)
  1-TOP w0.3: U3.1@93.48,52.05 92.55,52.05 92.3,52.3 92.3,53.7 92.55,53.95 U3.3@93.48,53.95
  1-TOP w0.5: U3.1@93.38,52.04 U3.1@93.48,52.04 ; v2@93.48,50.99 U3.1@93.48,52.04 ; U3.1@93.48,52.05 U3.1@93.48,52.04 ; R8.2@93.5,49.48 93.5,50.6 ; v2@94.56,51 v2(94.5,51) 94.6,50.9 R7.2@95.72,50.9 ; C8.2@95.6,52.04 U3.1@93.48,52.04
  1-TOP w1: 104.5,43.9 FIL1.3@106.1,43.9
  other v2: 103,42.1 104,42.1 105,42.1 103,43.1 104,43.1 105,43.1 93.5,51
VIN_PROT: C2.1 C3.2 C4.2 C12.2 C13.2 C14.2 C15.2 C139.1 C187.2 C197.2 C198.2 J6.1 R25.2 R27.2 R33.1 R154.2 R196.1 U1.8 U1.9 U1.10 U5.3 U6.3 U6.14 U7.B6 U7.E7 U19.7 U23.12 U32.A1 U32.A2 | length 125.1
  1-TOP w0.2: C198.2@80.76,-57.1 C197.2@80.76,-56 ; U6.14@82,40.1 U6.3@82.8,40.1 83.6,40.1 83.7,40.2 ; U23.12@83.1,-49.05 83.1,-49.7 83.2,-49.8 83.2,-50.16 C187.2@83.34,-50.3 83.3,-50.34 v1(83.3,-51) ; v1(111.3,19) R196.1@111.3,19.62
  1-TOP w0.3: U7.B6@-19.05,-11.43 -18.42,-10.8 -15.88,-10.8 U7.E7@-15.24,-10.16 ; v1(76.3,38.2) 76.32,38.22 R25.2@76.32,39 R25.2@76.32,39.1 ; U19.7@94.345,-47.57 94.345,-48.755 94.16,-48.94 C139.1@94.16,-49.5 v1(94.9,-49.5) ; v1(117.2,50.4) 117.22,50.42 R154.2@118.3,50.42
  1-TOP w0.4: v1(-19.685,-10.795) U7.B6@-19.05,-11.43 ; C198.2@80.76,-57.1 v2@81.6,-57.1 ; C197.2@80.76,-56 v2@81.6,-56
  1-TOP w0.8: J6.1@10.2,-42.196 10.539,-42.535 R33.1@12.4,-42.535
  3-INTOP w0.4: v1(-18.2,-38.9) 8.7,-38.9 10.2,-40.4 J6.1@10.2,-42.196
  6-INBOT w0.3: v1(94.2,43.5) 94.2,45.8 95.8,47.4 107.1,47.4 110.1,50.4 v1(117.2,50.4)
  6-INBOT w0.4: v1(-19.685,-10.795) -20.3,-11.41 -20.3,-36.8 v1@-18.201,-38.899 ; v1(-18.2,-38.9) v1(-17.4,-38.9)
  8-BOTTOM w0.4: v1(76.3,38.2) 77.9,38.2 80.4,40.7 v1(92.8,40.7)
  other v1: 96.7,27.08 97.4,27.08 96.7,28.08 97.4,28.08 93.5,40.7 94.2,40.7 92.8,41.4 93.5,41.4 94.2,41.4 92.8,42.1 93.5,42.1 94.2,42.1 92.8,42.8 93.5,42.8 94.2,42.8 92.8,43.5 93.5,43.5
  other v2: 81.8,-57.1 81.8,-56
VSYS: R34.2 U7.AL6 U7.AL7 U7.AL8 | length 5.1
  1-TOP w0.2: U7.AL6@17.78,-11.43 v1(18.415,-12.065) ; U7.AL7@17.78,-10.16 v1(18.415,-10.795) ; U7.AL8@17.78,-8.89 v1(18.415,-9.525)
  1-TOP w0.8: R34.2@8,-42.5 v2(8,-41.67) v2(8,-40.87) v2(8,-40.07)
VSYS2: R35.2 U7.AJ2 U7.AJ3 U7.AJ4 U7.AK2 U7.AK3 U7.AK4 | length 7.8
  1-TOP w0.2: U7.AJ2@15.24,-16.51 v1(15.875,-17.145) ; U7.AJ3@15.24,-15.24 v1(15.875,-15.875) ; U7.AJ4@15.24,-13.97 v1(15.875,-14.605) ; U7.AK2@16.51,-16.51 v1(17.145,-17.145) ; U7.AK3@16.51,-15.24 v1(17.145,-15.875) ; U7.AK4@16.51,-13.97 v1(17.145,-14.605)
  1-TOP w0.8: R35.2@6.4,-42.495 v2(6.4,-41.665) v2(6.4,-40.865) v2(6.4,-40.065)
WL_DEV_WAKE: J41.16 U7.F24 | length 119.2
  1-TOP w0.2: U7.F24@-13.97,11.43 v1(-13.335,12.065)
  3-INTOP w0.2: J41.16@-81.03,-36.85 -79.55,-36.85 -78.8,-37.6 -76.5,-37.6 -76.1,-38 -63.5,-38 -60.7,-35.2 -60.7,-31.4 -58.7,-29.4 -58.7,-27.6 -56.8,-25.7 -42.493,-25.7 -40.493,-23.7 -33.4,-23.7 -31.8,-25.3 -30.9,-26.2 -24.9,-26.2 -23.6,-24.9 -12.6,-24.9 v1(-12.1,-24.4)
  6-INBOT w0.2: v1(-13.335,12.065) -12.67,11.4 -11.9,11.4 -11.5,11 -11.5,-20.4 -12.1,-21 v1(-12.1,-24.4)
WL_HOST_WAKE: J41.18 U7.G18 | length 112
  1-TOP w0.2: v1(-13.335,4.445) U7.G18@-12.7,3.81
  3-INTOP w0.2: J41.18@-81.03,-39.39 -79.82,-40.6 -73.8,-40.6 -72.2,-39 -61.6,-39 -59.1,-36.5 -58,-36.5 -57.1,-35.6 -57.1,-31 -52.8,-26.7 -42.079,-26.7 -40.079,-24.7 -33.807,-24.7 -31.307,-27.2 -24.4,-27.2 -23.6,-26.4 -12.6,-26.4 v1(-12.1,-25.9)
  6-INBOT w0.2: v1(-13.335,4.445) -12.7,3.81 -12.7,-25 -12.1,-25.6 v1(-12.1,-25.9)
WLAN_SD3_CLK: J41.2 R52.2 | length 47.2
  1-TOP w0.2: v1(-46,-7.4) R52.2@-45.28,-7.4
  3-INTOP w0.2: J41.2@-81.03,-19.07 -78.67,-19.07 -77.7,-18.1 -77.7,-9.2 -74.2,-5.7 -48.6,-5.7 -46.9,-7.4 v1(-46,-7.4)
WLAN_SD3_CMD: J41.4 R53.2 | length 48.7
  1-TOP w0.2: v1(-46,-8.4) R53.2@-45.28,-8.4
  3-INTOP w0.2: J41.4@-81.03,-21.61 -79.63,-21.61 -77.2,-19.18 -77.2,-9.4 -74.1,-6.3 -52.8,-6.3 -50.7,-8.4 v1(-46,-8.4)
WLAN_SD3_D0: J41.6 R54.2 | length 49.9
  1-TOP w0.2: v1(-46,-9.4) R54.2@-45.28,-9.4
  3-INTOP w0.2: J41.6@-81.03,-24.15 -76.7,-19.82 -76.7,-9.6 -74,-6.9 -53,-6.9 -50.5,-9.4 v1(-46,-9.4)
WLAN_SD3_D1: J41.8 R55.2 | length 48.4
  1-TOP w0.2: v1(-46,-10.4) R55.2@-45.28,-10.4
  3-INTOP w0.2: J41.8@-81.03,-26.69 -76.2,-21.86 -76.2,-11.8 -75.6,-11.2 -67.2,-11.2 -66.6,-10.6 -47.4,-10.6 -47.2,-10.4 v1(-46,-10.4)
WLAN_SD3_D2: J41.10 R56.2 | length 50.8
  1-TOP w0.2: v1(-46,-11.4) R56.2@-45.28,-11.4
  3-INTOP w0.2: J41.10@-81.03,-29.23 -79.83,-29.23 -79.2,-28.6 -79.2,-26.1 -75.7,-22.6 -75.7,-12.5 -75,-11.8 -67,-11.8 -66.3,-11.1 -47.4,-11.1 -47.1,-11.4 v1(-46,-11.4)
WLAN_SD3_D3: J41.12 R57.2 | length 51.5
  1-TOP w0.2: v1(-46,-12.4) R57.2@-45.28,-12.4
  3-INTOP w0.2: J41.12@-81.03,-31.77 -78.53,-29.27 -78.53,-26.33 -75.2,-23 -75.2,-12.8 -74.8,-12.4 -47.2,-12.4 v1(-46,-12.4)
XBEE_RESET_N: J37.5 U7.E3 | length 176.2
  1-TOP w0.2: v1(-15.875,-15.875) U7.E3@-15.24,-15.24 ; J37.5@113.3,25.578 v1(113.3,27.3)
  3-INTOP w0.2: v1(-15.2,-22.9) 8.5,-22.9 9.9,-24.3 16.6,-24.3 17.1,-23.8 41.8,-23.8 45.9,-19.7 85.9,-19.7 95.6,-10 v1(101.6,-10)
  6-INBOT w0.2: v1(101.6,-10) 103,-10 104.9,-8.1 106,-7 106,-3.9 106,10.4 112.6,17 113.3,17.7 v1(113.3,27.3)
  8-BOTTOM w0.2: v1(-15.875,-15.875) -15.2,-16.55 -15.2,-19.4 v1(-15.2,-22.9)
XBEE_UART_CTS_1V8: J58.3 U35.4 | length 180
  1-TOP w0.2: v1(80.6,-9.4) U35.4@81.85,-9.4
  3-INTOP w0.2: J58.3@-64.52,2.5 -62.52,4.5 -44.4,4.5 -41.8,1.9 v1(-24.8,1.9)
  8-BOTTOM w0.2: v1(-24.8,1.9) -23.4,0.5 -23.4,-2.1 -19.1,-6.4 -19.1,-25.4 -17.7,-26.8 23.3,-26.8 40,-10.1 79,-10.1 79.7,-9.4 v1(80.6,-9.4)
XBEE_UART_CTS_3V3: J38.9 U35.1 | length 29.8
  1-TOP w0.2: U35.1@83.35,-9.4 v1(84.8,-9.4) ; J38.9@105.3,3.7 v1(105.3,5.4)
  8-BOTTOM w0.2: v1(84.8,-9.4) 85.5,-9.4 100.3,5.4 v1(105.3,5.4)
XBEE_UART_RTS_1V8: J59.3 U35.5 | length 167.8
  1-TOP w0.2: v1(80.2,-10) U35.5@81.85,-10
  3-INTOP w0.2: J59.3@-54.62,-3.2 -47.4,-3.2 -46.2,-2 -30.7,-2 -29.4,-0.7 v1(-24.1,-0.7)
  8-BOTTOM w0.2: v1(-24.1,-0.7) -24.1,-2.4 -20.3,-6.2 -20.3,-25.2 -18.2,-27.3 23.5,-27.3 40.1,-10.7 79.1,-10.7 79.8,-10 v1(80.2,-10)
XBEE_UART_RTS_3V3: J38.5 R198.2 U35.8 | length 40.3
  1-TOP w0.2: U35.8@83.35,-10 v1(84.2,-10) ; J38.5@113.3,3.7 v1(113.3,6.9)
  8-BOTTOM w0.2: v1@84.099,-10 85.7,-10 100.4,4.7 107.674,4.7 109.874,6.9 v1(113.3,6.9)
XBEE_UART_RX_1V8: J54.3 U34.4 | length 133.9
  1-TOP w0.2: v1(59.6,37.8) 59.9,37.5 U34.4@60.45,37.5
  3-INTOP w0.2: v1(-48,33.5) -47.3,33.5 -46.8,34 43.493,34 47.293,37.8 v1(59.6,37.8)
  6-INBOT w0.2: J54.3@-54.62,14.1 -52.3,14.1 -50.81,15.59 -50.81,29.618 -48,32.428 v1(-48,33.5)
XBEE_UART_RX_3V3: J37.2 U34.1 | length 68
  1-TOP w0.2: U34.1@61.95,37.5 v1(62.7,37.5) ; v1(116.5,27.4) 118.8,27.4 119.3,26.9 J37.2@119.3,22.85 J37.2@119.25,22.8
  3-INTOP w0.2: v1(62.7,37.5) 64.9,37.5 77.6,24.8 113.4,24.8 116,27.4 v1(116.5,27.4)
XBEE_UART_TX_1V8: J57.3 U34.5 | length 158.5
  1-TOP w0.2: v1(59,36.9) U34.5@60.45,36.9
  3-INTOP w0.2: v1(-46,33.5) 43.7,33.5 47.4,37.2 58.7,37.2 v1(59,36.9)
  6-INBOT w0.2: J57.3@-64.52,-3.2 -61.62,-0.3 -51.4,-0.3 -48.7,2.4 -48.7,28.8 -46,31.5 v1(-46,33.5)
XBEE_UART_TX_3V3: J37.3 U34.8 | length 64.1
  1-TOP w0.2: U34.8@61.95,36.9 62,36.9 62.433,36.9 62.633,36.7 v1(62.7,36.7) ; v1(117.3,22.8) J37.3@117.3,25.7
  3-INTOP w0.2: v1(62.7,36.7) 64.993,36.7 77.393,24.3 113.5,24.3 115,22.8 v1(117.3,22.8)
XBEE_USB_D_N: J37.8 L27.2 U25.4 | length 52.4
  1-TOP w0.168: U25.4@88.7,-16.15 89,-16.15 89.116,-16.034 89.116,-15.932 89.214,-15.834 89.572,-15.834 90.149,-15.834 90.459,-15.524 90.459,-15.282 90.557,-15.184 90.584,-15.184 90.7,-15.068 L27.2@90.7,-14.85 90.7,-14.568 90.458,-14.326 90.458,-13.292 90.458,6.408 104.459,20.409 104.459,22.234 106.9,24.675 107.811,24.675 108.011,24.475 108.011,24.336 107.3,23.625 J37.8@107.3,22.85
XBEE_USB_D_P: J37.7 L27.3 U25.5 | length 52.7
  1-TOP w0.168: U25.5@88.7,-15.2 89,-15.2 89.116,-15.316 89.116,-15.418 89.214,-15.516 89.44,-15.516 90.017,-15.516 90.115,-15.418 90.115,-15.278 90.021,-15.184 90.016,-15.184 89.9,-15.068 L27.3@89.9,-14.85 89.9,-14.568 90.14,-14.328 ; 90.14,-14.326 90.14,-13.16 90.14,6.54 104.141,20.541 104.141,22.366 106.768,24.993 107.943,24.993 108.327,24.609 108.984,24.609 109.3,24.925 J37.7@109.3,25.7
XBEE_VCC: C185.2 C186.2 J37.1 L38.2 L39.2 R197.2 | length 28.1
  1-TOP w0.5: R197.2@109.3,7.08 109.3,13.8 112.7,17.2 119,17.2 L38.2@121.1,17.2 ; L38.2@121.3,17 121.3,17.2 121.3,19.1 121.3,20.8 J37.1@121.3,25.15
pads on no net: D15.X D16.4 D16.5 D16.6 D16.7 FIDUCIAL1.1 FIDUCIAL2.1 FIDUCIAL3.1 FIDUCIAL4.1 FIDUCIAL5.1 FIDUCIAL6.1 J1.3 J1.4 J12.8 J12.9 J13.A2 J13.A3 J13.A5 J13.A8 J13.A10 J13.A11 J13.B2 J13.B3 J13.B5 J13.B8 J13.B10 J13.B11 J19.0 J19.3 J19.5 J19.7 J19.11 J19.13 J19.17 J19.19 J19.20 J19.22 J19.23 J19.25 J19.31 J19.33 J19.42 J19.44 J19.45 J19.46 J19.47 J19.49 J19.51 J19.H1 J19.H2 J19.MT1 J19.MT2 J20.7 J21.6 J21.7 J21.8 J22.4 J22.8 J22.9 J22.10 J26.MNT1 J26.MNT2 J27.MNT1 J27.MNT2 J29.M1 J29.M2 J30.4 J31.MT1 J31.MT21 J32.14 J37.9 J38.1 J38.2 J38.3 J38.4 J38.6 J38.8 J47.4 J63.A2 J63.A3 J63.A8 J63.A10 J63.A11 J63.B2 J63.B3 J63.B8 J63.B10 J63.B11 SWD.6 SWD.7 SWD.8 SWD.9 SWD.MT1 SWD.MT2 SWD.MT3 U7.A12 U7.AA29 U7.AB1 U7.AB29 U7.AC1 U7.AC29 U7.AD1 U7.AD29 U7.AE1 U7.AE29 U7.AG8 U7.AG9 U7.AG10 U7.AG11 U7.AG12 U7.AG13 U7.AG14 U7.AG15 U7.AG19 U7.AG22 U7.AG24 U7.AH9 U7.AH11 U7.AH18 U7.AH20 U7.AH22 U7.AH23 U7.AH24 U7.AH25 U7.AH26 U7.AH29 U7.AJ8 U7.AJ13 U7.AJ21 U7.AJ22 U7.AJ23 U7.AJ24 U7.AJ25 U7.AJ27 U7.AJ28 U7.AJ29 U7.AK21 U7.AK22 U7.AK26 U7.AK27 U7.AK28 U7.AK29 U7.AL28 U7.AM7 U7.AM8 U7.AM9 U7.AM16 U7.AM17 U7.AM22 U7.B7 U7.B9 U7.B10 U7.B12 U7.B13 U7.B16 U7.B17 U7.B23 U7.C3 U7.C7 U7.C8 U7.C9 U7.C11 U7.C27 U7.D1 U7.D7 U7.D10 U7.D13 U7.D14 U7.D15 U7.D19 U7.E16 U7.E24 U7.E25 U7.E26 U7.F3 U7.F9 U7.F10 U7.F19 U7.F23 U7.F25 U7.F26 U7.F27 U7.G3 U7.G4 U7.G6 U7.G7 U7.G9 U7.G10 U7.G20 U7.G21 U7.G23 U7.G24 U7.J29 U7.MH1 U7.MH2 U7.MH3 U7.MH4 U7.MH5 U7.MH6 U7.U1 U9.2 U9.6 U9.7 U9.14 U9.18 U9.19 U9.20 U9.21 U9.22 U13.1 U13.2 U13.4 U13.5 U13.13 U13.29 U13.31 U13.32 U14.1 U14.2 U14.4 U14.5 U14.13 U14.29 U14.31 U14.32 U15.7 U15.24 U16.1 U16.2 U16.7 U16.16 U16.17 U16.22 U16.23 U16.24 U17.15 U17.16 U17.19 U17.20 U17.37 U17.38 U17.39 U17.40 U17.43 U17.44 U17.45 U17.46 U17.47 U17.48 U17.58 U17.59 U17.60 U18.16 U20.18 U20.19 U20.20 U20.21 U21.4 U22.4 U23.2 U24.6 U25.6 U26.1 U26.6 U26.7 U26.8 U26.9 U26.11 U26.12 U26.13 U26.14 U27.11 U27.12 U27.13 U27.14 U27.28 U27.29 U27.40 U27.41 U27.46 U29.3 U29.6

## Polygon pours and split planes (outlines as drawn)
GND on 1-TOP "GND_PLANE" (solid, remove dead copper, pour order 54): -85.7,62.2 124.3,62.2 124.3,-67.8 -85.7,-67.8
5V on 1-TOP "NONET_L06_P-001" (solid, pour order 53): 95.64,-23.9 95.64,-25.9 97.64,-25.9 97.64,-23.9
3V3_ETH1 on 1-TOP "NONET_L06_P-001" (solid, pour order 19): -64.6,-26.4 -64.6,-24.4 -67.4,-24.4 -67.4,-26.4
3V3_ETH2 on 1-TOP "NONET_L06_P-001" (solid, pour order 52): -35.8,-41.13 -38.6,-41.13 -38.6,-43.13 -35.8,-43.13
3V3_SOM_EXT on 1-TOP "NONET_L06_P-001" (solid, pour order 51): -38.6,-45.47 -35.8,-45.47 -35.8,-43.47 -38.6,-43.47
NetD21_A on 1-TOP "NONET_L06_P-001" (solid, pour order 50): 82.5,-54.7 82.5,-57.6 84.2,-57.6 84.2,-56.2 83.5,-55.5 83.5,-54.7
VIN_PROT on 1-TOP "NONET_L06_P-001" (solid, pour order 49): 82.4,-54.1 82.4,-57.6 80.4,-57.6 80.3,-57.5 80.3,-55.4 81.1,-55.4 81.5,-55 81.5,-54.1
USBC_VBUS on 1-TOP "NONET_L06_P-001" (solid, pour order 48): 85.2,-55.5 85.6,-55.9 85.6,-57.6 87.9,-57.6 87.9,-54.3 87.7,-54.1 83.6,-54.1 83.6,-55.5
5V on 1-TOP "NONET_L06_P-001" (solid, pour order 46): 38.6,-48.1 36.6,-48.1 36.6,-49.82 38.6,-49.82
5V_DBG on 1-TOP "NONET_L06_P-001" (solid, pour order 45): -39.2,43.8 -32.3,43.8 -32.3,45.7 -39.2,45.7
NetC16_1 on 1-TOP "NONET_L06_P-001" (solid, pour order 11): 94.6,28.6 93.9,28.6 93.4,28.1 87.8,28.1 87.8,30.5 94.6,30.5
1V8_PHY_2 on 1-TOP "NONET_L06_P-001" (solid, pour order 24): -46.2,-33.4 -43.5,-33.4 -43.5,-31.4 -44.2,-31.4
3V3_BOARD on 1-TOP "3V3_BOARD" (solid, remove dead copper, pour order 1): 87.5,31.3 87.7,31.1 94.5,31.1 95.9,32.5 95.9,34.9 95.7,35.1 87.7,35.1 87.5,34.9
VIN on 1-TOP "VIN" (solid, remove dead copper, pour order 3): 105.5,46 101.4,46 99.3,43.9 97.9,43.9 97.9,42.5 98.5,41.9 98.5,40.9 98.6,40.8 100.1,40.8 101,41.7 105.5,41.7
VIN_PROT on 1-TOP "VIN_PROT" (solid, remove dead copper, pour order 2): 85.6,42.1 85.6,43.2 86.3,43.9 95.7,43.9 95.9,43.7 95.9,37.9 95.7,37.7 93.2,37.7 90.9,40 84.5,40 83,40 85.1,42.1
1V8 on 1-TOP "NONET_L06_P-001" (solid, pour order 41): -35.1,18.1 -35.8,18.8 -35.1,19.5 -35.1,19.9 -32.9,19.9 -32.9,17.8 -35.1,17.8
1V8_SOM_EXT on 1-TOP "NONET_L06_P-001" (solid, pour order 37): -15.054,-45.47 -12.254,-45.47 -12.254,-43.47 -15.054,-43.47
1V8 on 1-TOP "NONET_L06_P-001" (solid, pour order 40): -12.254,-41.13 -15.054,-41.13 -15.054,-43.13 -12.254,-43.13
3V3_SOM_EXT on 1-TOP "NONET_L06_P-001" (solid, pour order 36): -32.6,-45.47 -29.8,-45.47 -29.8,-43.47 -32.6,-43.47
3V3 on 1-TOP "NONET_L06_P-001" (solid, pour order 35): -29.8,-41.13 -32.6,-41.13 -32.6,-43.13 -29.8,-43.13
NetJ6_2 on 1-TOP "NONET_L06_P-001" (solid, pour order 34): 5.3,-43.608 13.2,-43.608 13.2,-46.408 5.3,-46.408
VIN_PROT on 1-TOP "NONET_L06_P-001" (solid, pour order 12): 95.6,28.4 95.6,26.7 97.8,26.7 97.8,28.4
NetC148_2 on 1-TOP "NONET_L06_P-001" (solid, pour order 32): 114.9,-35.5 114.9,-33.45 111.5,-33.45 111.5,-35.5
3V3_USB on 1-TOP "NONET_L06_P-001" (solid, pour order 31): 111.5,-30.9 111.5,-32.95 114.9,-32.95 114.9,-30.9
3V3_SOM_EXT on 1-TOP "NONET_L06_P-001" (solid, pour order 30): 92.9,-30.5 92.9,-33.3 94.9,-33.3 94.9,-30.5
3V3_USB on 1-TOP "NONET_L06_P-001" (solid, pour order 29): 97.3,-30.5 95.3,-30.5 95.3,-33.3 97.3,-33.3
1V8_SOM_EXT on 1-TOP "NONET_L06_P-001" (solid, pour order 28): -49.9,36.3 -51.9,36.3 -51.9,33.5 -49.9,33.5
3V3_CODEC on 1-TOP "NONET_L06_P-001" (solid, pour order 27): -53.5,27.9 -56.3,27.9 -56.3,25.9 -53.5,25.9
3V3_SOM_EXT on 1-TOP "NONET_L06_P-001" (solid, pour order 26): -53.5,23.5 -53.5,25.5 -56.3,25.5 -56.3,23.5
1V8_PHY_1 on 1-TOP "NONET_L06_P-001" (solid, pour order 25): -65.1,-33.2 -63.4,-31.5 -62.1,-31.5 -62.1,-33.2
3V3_ETH2 on 1-TOP "NONET_L06_P-001" (solid, pour order 23): -41,-43.1 -43,-43.1 -43,-45 -41,-45
3V3_ETH1 on 1-TOP "NONET_L06_P-001" (solid, pour order 22): -60.395,-42.6 -62.395,-42.6 -62.395,-44.6 -60.395,-44.6
3V3_SOM_EXT on 1-TOP "NONET_L06_P-001" (solid, pour order 20): -64.6,-22 -67.4,-22 -67.4,-24 -64.6,-24
CT2 on 1-TOP "AGND" (solid, remove dead copper, pour order 18): -57.3,-45.952 -52.845,-45.952 -52.845,-48.752 -54.245,-48.752 -54.245,-47.952 -54.945,-47.252 -57.3,-47.252
CT1 on 1-TOP "AGND" (solid, remove dead copper, pour order 17): -79.315,-45.952 -74.315,-45.952 -74.315,-48.752 -75.715,-48.752 -75.715,-47.952 -76.415,-47.252 -78.815,-47.252 -79.315,-46.752
5V on 1-TOP "NONET_L06_P-001" (solid, pour order 15): 8.6,-55.6 8.6,-58.2 11.3,-58.2 11.3,-55.6
5V on 1-TOP "NONET_L06_P-001" (solid, pour order 14): 87.4,30.3 87.4,27.2 85.5,27.2 85.5,30.3
VIN on 1-TOP "NONET_L06_P-001" (solid, pour order 13): 92.8,52.4 96.2,52.4 96.2,50.4 92.8,50.4
3V3 on 1-TOP "NONET_L06_P-001" (solid, pour order 10): -44,39.3 -44,41.4 -46.1,41.4 -46.1,39.3
3V3_DBG on 1-TOP "NONET_L06_P-001" (solid, pour order 9): -48.6,39.3 -46.5,39.3 -46.5,41.4 -48.6,41.4
3V3_DBG on 1-TOP "NONET_L06_P-001" (solid, pour order 8): -48.6,43.8 -48.6,41.7 -46.5,41.7 -46.5,43.8
3V3_DBG on 1-TOP "3V3_DBG" (solid, remove dead copper, pour order 5): -42.65,52.5 -43.3,52.5 -43.3,58.2 -42.2,58.2 -41.6,57.6 -41.6,52.5 -42.05,52.5
NetFIL1_1 on 1-TOP "NONET_L06_P-001" (solid, pour order 4): 98.9,57.4 107.6,48.7 107.6,46.3 108.2,45.7 109.8,45.7 109.8,41.7 113.3,41.7 114.7,43.1 114.7,61.6 98.9,61.6
GND on 8-BOTTOM "GND_PLANE" (solid, remove dead copper, pour order 44): -85.7,62.2 124.3,62.2 124.3,-67.8 -85.7,-67.8
GND on 6-INBOT "GND_PLANE" (solid, remove dead copper, pour order 43): -85.7,62.2 124.3,62.2 124.3,-67.8 -85.7,-67.8
1V8 on 6-INBOT "NONET_L06_P-001" (solid, pour order 39): -35.1,19.95 -35.1,17.85 -34.8,17.85 -34.4,17.45 -33.6,17.45 -33.2,17.85 -32.9,17.85 -32.9,19.95
1V8 on 6-INBOT "NONET_L06_P-001" (solid, pour order 38): -18.3,-39.7 -19.05,-40.45 -18.4,-41.1 -18.4,-43.295 -12.206,-43.295 -12.206,-39.7
GND on 3-INTOP "GND_PLANE" (solid, remove dead copper, pour order 42): -85.7,62.2 124.3,62.2 124.3,-67.8 -85.7,-67.8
